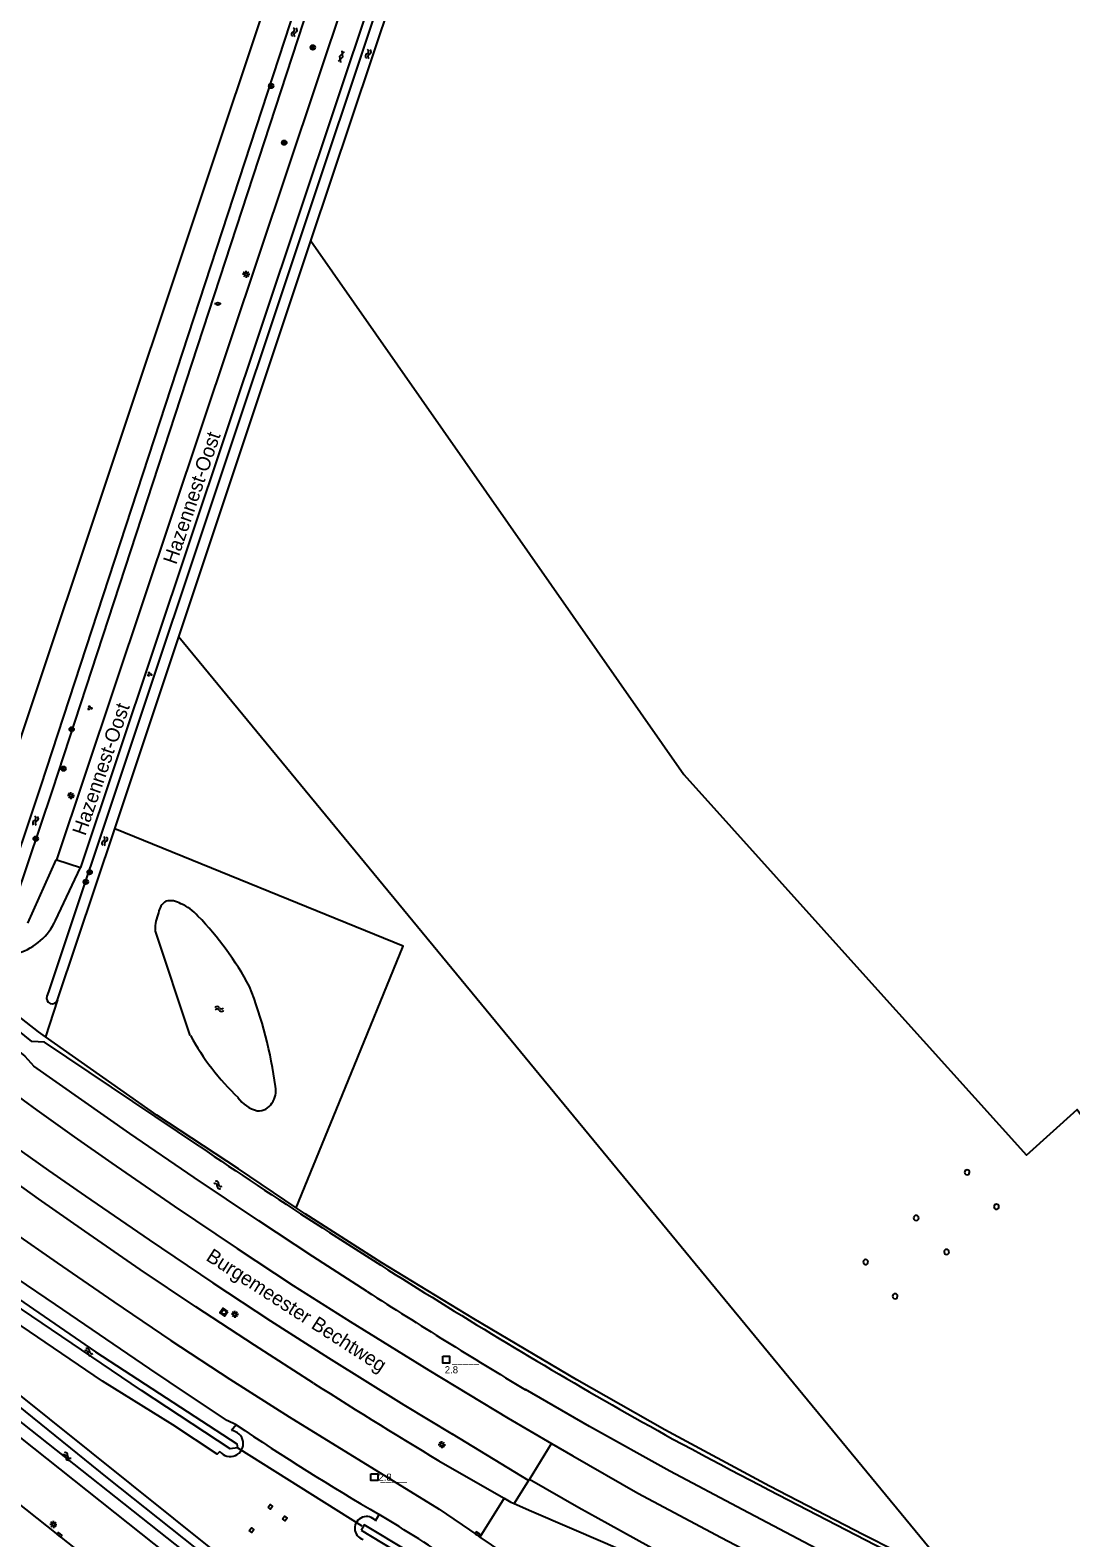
# Model space of a CAD drawing. Extents: x 136000 to 138005, y 398500 to 400500.
# Drawn here: x 136222.9 to 136405.4, y 399123.7 to 399387.9 of the extents above; entities that cross this region are included whole.
import ezdxf

# ---------------------------------------------------------------- set-up
doc = ezdxf.new("R2010")
doc.units = 0
for name, color, linetype in [('gg-afsc-erfafscheiding', 7, 'Continuous'), ('gg-afsc-faunaraster', 7, 'Continuous'), ('gg-afsc-hekwerk', 7, 'Continuous'), ('gg-anno-openbare ruimte label', 7, 'Continuous'), ('gg-bbg-hoogspanningsmast', 7, 'Continuous'), ('gg-knt-bovenkant onderkant talud', 7, 'Continuous'), ('gg-knt-bronhoudergrens', 7, 'Continuous'), ('gg-knt-onverhard', 7, 'Continuous'), ('gg-knt-verharding', 7, 'Continuous'), ('gg-kntw-bovenkant insteek waterloop', 7, 'Continuous'), ('gg-kntw-waterlijn', 7, 'Continuous'), ('gg-kwrk-duiker nz buis', 7, 'Continuous'), ('gt-anno-nummer hm paal', 7, 'Continuous'), ('gt-grn-groengrens', 7, 'Continuous'), ('gt-grn-weggrens', 7, 'Continuous'), ('gt-symb-boom', 7, 'Continuous'), ('gt-symb-gesloten verharding', 7, 'Continuous'), ('gt-symb-groenvak', 7, 'Continuous'), ('gt-symb-hm paal', 7, 'Continuous'), ('gt-symb-kolk', 7, 'Continuous'), ('gt-symb-lichtmast', 7, 'Continuous'), ('gt-symb-peilbuis', 7, 'Continuous'), ('gt-symb-rioolschacht', 7, 'Continuous'), ('gt-symb-watersymbool', 7, 'Continuous')]:
    doc.layers.add(name, color=color, linetype=linetype)

# ---------------------------------------------------------------- blocks, each defined once
blk = doc.blocks.new('gt0-BOOM')
at = {"layer": 'gt-symb-boom'}
for radius in [0.4, 0.2]:
    blk.add_circle((0, 0), radius, dxfattribs=at)
blk = doc.blocks.new('gt0-WA')
at = {"layer": 'gt-symb-watersymbool'}
for centre, start, end in [((-0.32, 0.02), 28.0725, 151.9275), ((0.43, 0.42), 208.0725, 331.9275), ((-0.32, -0.43), 28.0725, 151.9275), ((0.43, -0.03), 208.0725, 331.9275)]:
    blk.add_arc(centre, 0.425, start, end, dxfattribs=at)
blk = doc.blocks.new('gt0-GESVH1')
at = {"layer": 'gt-symb-gesloten verharding'}
for p, q in [((-0.99, -0.26), (0.01, 0.24)), ((0.01, -0.26), (-0.99, 0.24)), ((0.01, 0.24), (1.01, -0.26)), ((1.01, 0.24), (0.01, -0.26))]:
    blk.add_line(p, q, dxfattribs=at)
blk = doc.blocks.new('gt0-LMAST')
at = {"layer": 'gt-symb-lichtmast'}
for p, q in [((-0.18, 0.17), (-0.45, 0.44)), ((-0.01, 0.25), (-0.01, 0.62)), ((0.17, 0.17), (0.44, 0.44)), ((-0.26, 0), (-0.63, 0)), ((-0.18, -0.18), (-0.45, -0.45)), ((-0.01, -0.25), (-0.01, -0.63)), ((0.44, -0.45), (0.17, -0.18)), ((0.24, 0), (0.62, 0))]:
    blk.add_line(p, q, dxfattribs=at)
blk.add_circle((-0.01, 0), 0.25, dxfattribs=at)
blk = doc.blocks.new('gt0-KOLK')
at = {"layer": 'gt-symb-kolk'}
blk.add_lwpolyline([(0, 0), (0.37, 0), (0.37, 0.4), (-0.38, 0.4), (-0.38, 0), (0, 0)], dxfattribs=at)
blk = doc.blocks.new('gt0-HMpaal')
at = {"layer": 'gt-symb-hm paal'}
blk.add_lwpolyline([(-0.6, 0.6), (0.6, 0.6), (0.6, -0.6), (-0.6, -0.6)], close=True, dxfattribs=at)
blk = doc.blocks.new('gt0-GRVAK')
at = {"layer": 'gt-symb-groenvak'}
for p, q in [((-0.11, 0.19), (-0.23, 0.24)), ((-0.18, 0.15), (0.09, 0.15)), ((-0.09, 0.21), (-0.16, 0.32)), ((-0.05, 0.21), (-0.05, 0.39)), ((0, 0.21), (0.06, 0.32)), ((0.01, 0.19), (0.13, 0.24)), ((0.26, -0.05), (0.2, 0.06)), ((0.3, -0.05), (0.3, 0.13)), ((0.35, -0.05), (0.41, 0.06)), ((-0.24, -0.23), (-0.36, -0.18)), ((-0.32, -0.26), (-0.05, -0.26)), ((-0.23, -0.21), (-0.29, -0.1)), ((-0.18, -0.2), (-0.18, -0.02)), ((-0.14, -0.21), (-0.07, -0.1)), ((-0.12, -0.23), (0, -0.18)), ((0.24, -0.07), (0.12, -0.02)), ((0.17, -0.11), (0.44, -0.11)), ((0.37, -0.07), (0.49, -0.02))]:
    blk.add_line(p, q, dxfattribs=at)
blk = doc.blocks.new('gt0-PBUIS')
at = {"layer": 'gt-symb-peilbuis'}
blk.add_circle((0, 0), 0.25, dxfattribs=at)
for centre, start, end in [((-0.21, 0), 141.9073, 218.0927), ((0.21, 0), 321.9073, 38.0927)]:
    blk.add_arc(centre, 0.243, start, end, dxfattribs=at)
blk = doc.blocks.new('gt0-RS')
at = {"layer": 'gt-symb-rioolschacht'}
blk.add_lwpolyline([(-0.5, -0.5), (0.5, -0.5), (0.5, 0.5), (-0.5, 0.5)], close=True, dxfattribs=at)
blk.add_circle((0, 0), 0.375, dxfattribs=at)

msp = doc.modelspace()

# ---------------------------------------------------------------- linework, layer by layer
at = {"layer": 'gg-afsc-erfafscheiding'}
for points in [[(136269.57, 399181.49), (136259.44, 399188.32), (136245.15, 399197.75)], [(136385.71, 399115.76), (136369.04, 399124.19), (136352.59, 399132.73), (136334.23, 399142.59), (136318.79, 399151.34), (136300.7, 399162.06), (136284.59, 399171.85), (136271.13, 399180.44), (136269.57, 399181.49)]]:
    msp.add_lwpolyline(points, dxfattribs=at)
at = {"layer": 'gg-afsc-faunaraster'}
msp.add_line((136245.15, 399197.75), (136225.59, 399211.48), dxfattribs=at)
msp.add_lwpolyline([(136225.59, 399211.48), (136224.38, 399212.33), (136214.32, 399220.19)], dxfattribs=at)
at = {"layer": 'gg-afsc-hekwerk'}
msp.add_lwpolyline([(136216.64, 399250.09), (136221.87, 399265.6), (136281.27, 399443.5)], dxfattribs=at)
at = {"layer": 'gg-bbg-hoogspanningsmast'}
for points in [[(136264.63, 399129.03), (136264.99, 399129.48), (136265.43, 399129.13), (136265.06, 399128.68), (136264.63, 399129.03)], [(136267.19, 399126.98), (136267.55, 399127.43), (136267.98, 399127.08), (136267.62, 399126.63), (136267.19, 399126.98)], [(136261.35, 399124.94), (136261.71, 399125.39), (136262.15, 399125.04), (136261.79, 399124.59), (136261.35, 399124.94)]]:
    msp.add_lwpolyline(points, dxfattribs=at)
for centre, start, end in [((136387.23, 399187.72), 359.8704, 179.8704), ((136387.23, 399187.72), 179.8704, 359.8704), ((136392.36, 399181.7), 0, 180), ((136392.36, 399181.7), 180, 0), ((136378.3, 399179.74), 359.8704, 179.8704), ((136378.3, 399179.74), 179.8704, 359.8704), ((136383.63, 399173.78), 359.8704, 179.8704), ((136383.63, 399173.78), 179.8704, 359.8704), ((136369.44, 399171.99), 0.1298, 180.259), ((136369.44, 399171.99), 180.259, 0.1298), ((136374.6, 399166), 359.8704, 179.8704), ((136374.6, 399166), 179.8704, 359.8704)]:
    msp.add_arc(centre, 0.442, start, end, dxfattribs=at)
at = {"layer": 'gg-knt-bovenkant onderkant talud'}
msp.add_arc((136509.43, 399515.08), 448.1, 236.0258, 239.8142, dxfattribs=at)
at = {"layer": 'gg-knt-bronhoudergrens'}
msp.add_line((136227.74, 399217.93), (136225.59, 399211.48), dxfattribs=at)
msp.add_lwpolyline([(136269.57, 399181.49), (136278.67, 399203.74), (136288.33, 399227.36), (136237.75, 399247.91)], dxfattribs=at)
at = {"layer": 'gg-knt-onverhard'}
for p, q in [((136222.5, 399231.4), (136227.49, 399242.49)), ((136227.36, 399231.88), (136231.76, 399241.17))]:
    msp.add_line(p, q, dxfattribs=at)
msp.add_arc((136217.71, 399236.29), 10.61, 239.5857, 335.4534, dxfattribs=at)
at = {"layer": 'gg-knt-verharding'}
for p, q in [((136299.15, 399442.57), (136231.76, 399241.17)), ((136227.59, 399242.46), (136292.76, 399437.13)), ((136227.49, 399242.49), (136227.59, 399242.46)), ((136227.59, 399242.46), (136231.76, 399241.17)), ((136310.29, 399133.71), (136296.98, 399141.83)), ((136296.09, 399136.28), (136306.04, 399130.59)), ((136310.29, 399133.71), (136307.82, 399129.66)), ((136310.48, 399133.91), (136310.29, 399133.71))]:
    msp.add_line(p, q, dxfattribs=at)
for points in [[(136088.11, 399295.8), (136207.72, 399201.36), (136219.72, 399192.61), (136226.15, 399188.05), (136232.62, 399183.56), (136243.77, 399175.91), (136254.97, 399168.35), (136265.05, 399161.7), (136275.23, 399155.19), (136288.44, 399146.99), (136296.98, 399141.83)], [(136070.34, 399293.96), (136070.79, 399293.6), (136203.45, 399189.11), (136211.91, 399182.91), (136219.76, 399177.36), (136227.64, 399171.86), (136237.57, 399165.01), (136247.57, 399158.25), (136257.91, 399151.48), (136268.33, 399144.85), (136294.65, 399128.7)], [(136272.63, 399150.78), (136262.28, 399157.4), (136252, 399164.14), (136242.23, 399170.71), (136232.52, 399177.38), (136224.41, 399183.05), (136216.35, 399188.78), (136207.92, 399194.94), (136084.97, 399291.82)], [(136214.46, 399205.6), (136224.11, 399198.59), (136230.66, 399193.92), (136237.26, 399189.3), (136248.19, 399181.79), (136259.2, 399174.38), (136269.07, 399167.9), (136279.04, 399161.55), (136292.84, 399153.02), (136306.72, 399144.64), (136314.32, 399140.21)], [(136197.17, 399148.36), (136212.69, 399136.13), (136294.92, 399070.89), (136308.79, 399060.14), (136313.55, 399056.62), (136342.22, 399036.62), (136349.12, 399031.63), (136358.25, 399024.75), (136367.82, 399017.16)], [(136314.32, 399140.21), (136318.07, 399138.02), (136329.47, 399131.49)], [(136408.2, 399086.18), (136387.91, 399094.64), (136380.53, 399097.78), (136362.41, 399105.89), (136353.35, 399110.43), (136343.58, 399115.45), (136324.2, 399126.09), (136319.14, 399128.9), (136310.48, 399133.91)], [(136329.47, 399131.49), (136344.1, 399123.71), (136359.6, 399115.61), (136390.29, 399101.98), (136396.58, 399099.15), (136398.77, 399098.3), (136406.98, 399094.65), (136411.61, 399092.7)], [(136294.65, 399128.7), (136301.25, 399124.16), (136301.8, 399123.79)], [(136306.04, 399130.59), (136307.19, 399129.93), (136307.82, 399129.66)], [(136307.82, 399129.66), (136310.84, 399128.34), (136323.73, 399122.79), (136335.42, 399117.68), (136339.86, 399115.72), (136343.61, 399113.61), (136354.1, 399107.85), (136366.25, 399101.61), (136376.95, 399096.3), (136388.1, 399090.9), (136398.06, 399086.22), (136406.44, 399082.34)], [(136301.8, 399123.79), (136315.35, 399114.59), (136321.62, 399110.51), (136328.82, 399106.1), (136342.72, 399098.17), (136350.22, 399094.22), (136357.73, 399090.32), (136371.23, 399083.64), (136385.61, 399076.74), (136393.33, 399073.18), (136397.89, 399071.09), (136400.06, 399069.99), (136400.58, 399069.76), (136400.62, 399069.73)]]:
    msp.add_lwpolyline(points, dxfattribs=at)
msp.add_arc((136840.43, 400043.14), 1057.69, 237.53174, 239.02568, dxfattribs=at)
at = {"layer": 'gg-kntw-bovenkant insteek waterloop'}
for p, q in [((136272.17, 399350.96), (136321.95, 399500)), ((136300.51, 399442.11), (136226.11, 399219.35)), ((136248.99, 399281.56), (136272.17, 399350.96)), ((136237.75, 399247.91), (136248.99, 399281.56)), ((136227.74, 399217.93), (136237.75, 399247.91)), ((136251, 399211.72), (136244.82, 399230.19)), ((136226.11, 399219.35), (136225.83, 399218.61)), ((136252.68, 399192.23), (136225.44, 399210.52)), ((136259.02, 399143.48), (136258.2, 399142.45)), ((136283.51, 399126.62), (136284.12, 399127.74))]:
    msp.add_line(p, q, dxfattribs=at)
for points in [[(136285.36, 399440.73), (136224.79, 399255.54), (136218.11, 399235.6)], [(136220.36, 399235.37), (136226.87, 399254.84), (136287.45, 399440.05), (136285.36, 399440.73)], [(136000, 399382.44), (136021.42, 399365.77), (136066.43, 399330.42), (136131.09, 399279.49), (136164.07, 399253.35), (136198.12, 399226.05), (136212.68, 399215.58), (136221.96, 399208.08), (136223.57, 399206.33)], [(136225.44, 399210.52), (136223.23, 399210.64), (136214.55, 399217.59), (136214.32, 399220.19)], [(136282, 399166.84), (136272.48, 399172.97), (136263.03, 399179.22), (136251.67, 399186.82), (136240.37, 399194.51), (136223.57, 399206.33)], [(136259.02, 399143.48), (136257.46, 399144.22), (136250.66, 399148.72), (136243.9, 399153.28), (136227.37, 399164.56), (136213.88, 399173.65)], [(136256.19, 399138.8), (136255.72, 399138.34), (136247.96, 399143.44), (136235.59, 399151.09), (136221.32, 399160.82), (136214.36, 399165.48), (136211.73, 399161.9)], [(136207.1, 399160.33), (136209.3, 399158.6), (136212.24, 399156.22), (136218.91, 399150.43), (136255.41, 399121.16), (136310.73, 399077.53), (136313.04, 399075.63), (136315.41, 399073.82), (136320.69, 399069.94), (136327.09, 399065.06), (136330.87, 399062.31), (136334.73, 399059.66), (136336.69, 399058.13), (136338.74, 399056.73), (136345.98, 399052.14), (136349.62, 399049.69), (136360.51, 399041.94), (136364.14, 399039.14), (136367.72, 399036.25), (136370.83, 399033.67)], [(136328.24, 399057.37), (136301.4, 399077.49), (136206.94, 399152.55), (136203.47, 399155.23)], [(136399.74, 399102.57), (136394.67, 399104.87), (136385.29, 399109.3), (136372.99, 399115.5), (136360.75, 399121.8), (136347.91, 399128.54), (136335.1, 399135.33), (136321.02, 399143.18), (136309.78, 399149.63)]]:
    msp.add_lwpolyline(points, dxfattribs=at)
for centre, radius, start, end in [((136248.34, 399232.78), 2.95, 123.5395, 171.3785), ((136247.5, 399231.91), 3.42, 57.0438, 103.4304), ((136246.08, 399227.12), 8.34, 41.426, 66.8044), ((136253.13, 399230.12), 8.31, 158.0914, 179.5142), ((136210.57, 399192.46), 57.96, 28.6976, 43.8904), ((136226.79, 399218.29), 1.02, 161.7313, 339.1319), ((136190.42, 399192.52), 76.22, 7.7094, 21.3631), ((136290.08, 399233.09), 44.53, 208.6794, 226.4033), ((136262.38, 399202.02), 3.65, 323.6779, 11.3951), ((136264.37, 399204.44), 6.17, 215.7411, 254.7895), ((136262.9, 399201.29), 2.81, 267.0752, 329.4383), ((136883.72, 400120.89), 1122.78, 235.80355, 238.27971), ((136930.84, 400183.18), 1205.8, 237.44583, 238.99872), ((136787.61, 399957.11), 932.93, 238.01208, 241.02329), ((136258.01, 399140.18), 2.28, 217.1953, 85.1289), ((137295.62, 400936.82), 2036.33, 241.87332, 243.58765), ((136281.89, 399125.35), 2.05, 38.1917, 254.2248), ((136090.63, 398805.58), 375.8, 54.0345, 59.011)]:
    msp.add_arc(centre, radius, start, end, dxfattribs=at)
at = {"layer": 'gg-kntw-waterlijn'}
for points in [[(136210.37, 399165.4), (136213.71, 399169.89), (136216.3, 399168.67), (136234.35, 399156.25), (136259.17, 399140.13), (136259.28, 399139.46), (136257.99, 399139.24), (136242.47, 399149.49), (136214.47, 399168.41), (136213.89, 399168.59), (136211.18, 399164.89)], [(136374.22, 399031.03), (136371.95, 399031.03), (136360.33, 399040.11), (136354.36, 399044.43), (136342.99, 399052.09), (136336.83, 399056.08), (136328.77, 399061.96), (136319.41, 399069.08), (136308, 399077.77), (136290.33, 399091.45), (136277.62, 399101.43), (136269.1, 399108.3), (136258.72, 399116.53), (136236.48, 399134.15), (136206.42, 399158.41), (136205.96, 399158.74)], [(136375.99, 399029.65), (136374.67, 399028.25), (136374.16, 399027.72), (136373.42, 399027.65), (136356.66, 399040.81), (136348.76, 399046.68), (136338.18, 399053.53), (136332.62, 399057.41), (136325.02, 399062.71), (136317.67, 399068.35), (136289.24, 399090.18), (136251.46, 399120.07), (136218.52, 399146.14), (136205.61, 399156.81), (136204.94, 399157.3)], [(136280.94, 399124.99), (136291.97, 399118.32), (136309.19, 399106.88), (136321.62, 399098.29), (136330.93, 399093.3), (136354.21, 399080.82), (136355.2, 399081.07), (136355.46, 399081.6), (136354.88, 399082.34), (136341.27, 399089.52), (136322.36, 399099.5), (136299.71, 399114.67), (136289.29, 399121.29), (136281.5, 399125.93), (136280.94, 399124.99)]]:
    msp.add_lwpolyline(points, dxfattribs=at)
at = {"layer": 'gg-kwrk-duiker nz buis'}
msp.add_line((136281.12, 399125.71), (136259.28, 399139.46), dxfattribs=at)
at = {"layer": 'gt-grn-groengrens'}
msp.add_line((136248.99, 399281.56), (136385.71, 399115.76), dxfattribs=at)
msp.add_lwpolyline([(136272.17, 399350.96), (136337.56, 399257.42), (136370.46, 399220.87), (136397.62, 399190.7), (136406.53, 399198.72), (136422.84, 399175.76)], dxfattribs=at)
at = {"layer": 'gt-grn-weggrens'}
for p, q in [((136310.48, 399133.91), (136314.32, 399140.21)), ((136306.04, 399130.59), (136301.8, 399123.79))]:
    msp.add_line(p, q, dxfattribs=at)

# ---------------------------------------------------------------- block references
at = {"layer": 'gt-symb-boom'}
for p in [(136272.49, 399384.87), (136265.18, 399378.12), (136267.48, 399368.18), (136230.19, 399265.36), (136228.75, 399258.47), (136223.9, 399246.2), (136233.35, 399240.33), (136232.68, 399238.63)]:
    msp.add_blockref('gt0-BOOM', p, dxfattribs=at)
at = {"layer": 'gt-symb-gesloten verharding', "rotation": 71.69193184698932}
msp.add_blockref('gt0-GESVH1', (136277.46, 399383.26), dxfattribs=at)
at = {"layer": 'gt-symb-groenvak'}
for p in [(136243.85, 399275.03), (136233.38, 399269.13)]:
    msp.add_blockref('gt0-GRVAK', p, dxfattribs=at)
at = {"layer": 'gt-symb-hm paal'}
for p in [(136295.87, 399154.9), (136283.27, 399134.29)]:
    msp.add_blockref('gt0-HMpaal', p, dxfattribs=at)
at = {"layer": 'gt-symb-kolk'}
for p, rotation in [((136227.94, 399124.03), -38.46294706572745), ((136301.25, 399124.16), -33.57881372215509)]:
    msp.add_blockref('gt0-KOLK', p, dxfattribs=dict(at, rotation=rotation))
at = {"layer": 'gt-symb-lichtmast'}
for p in [(136260.81, 399345.12), (136230.09, 399253.75), (136258.84, 399162.84), (136295.13, 399139.99), (136227, 399126)]:
    msp.add_blockref('gt0-LMAST', p, dxfattribs=at)
at = {"layer": 'gt-symb-peilbuis'}
msp.add_blockref('gt0-PBUIS', (136255.84, 399339.94), dxfattribs=at)
at = {"layer": 'gt-symb-rioolschacht', "rotation": 146.08748741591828}
msp.add_blockref('gt0-RS', (136256.89, 399163.21), dxfattribs=at)
at = {"layer": 'gt-symb-watersymbool'}
for p, rotation in [((136269.25, 399387.6), -98.51093419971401), ((136282.23, 399383.77), -98.51093419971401), ((136223.88, 399249.4), -98.51093420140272), ((136236, 399245.83), -98.51093419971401), ((136255.81, 399185.54), -33.499400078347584), ((136233.14, 399156.25), -33.499400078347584), ((136229.31, 399137.96), -37.52317188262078)]:
    msp.add_blockref('gt0-WA', p, dxfattribs=dict(at, rotation=rotation))
msp.add_blockref('gt0-WA', (136256.04, 399216.35), dxfattribs=at)

# ---------------------------------------------------------------- texts
at = {"layer": 'gg-anno-openbare ruimte label'}
for s, rotation, p in [('Hazennest-Oost', 71.1, (136248.52, 399294.11)), ('Hazennest-Oost', 71.1, (136232.6, 399246.58)), ('Burgemeester Bechtweg', 327.2, (136253.59, 399172.41))]:
    msp.add_text(s, height=2.5, rotation=rotation, dxfattribs=at).set_placement(p)
at = {"layer": 'gt-anno-nummer hm paal'}
for p in [(136295.63, 399152.49), (136284, 399133.67)]:
    msp.add_text('2.8', height=1.25, dxfattribs=at).set_placement(p)
at = {"layer": 'gt-symb-hm paal'}
for p in [(136296.95, 399154.29), (136284.36, 399133.68)]:
    msp.add_text('_____', height=1.25, dxfattribs=at).set_placement(p)

doc.saveas('drawing.dxf')
